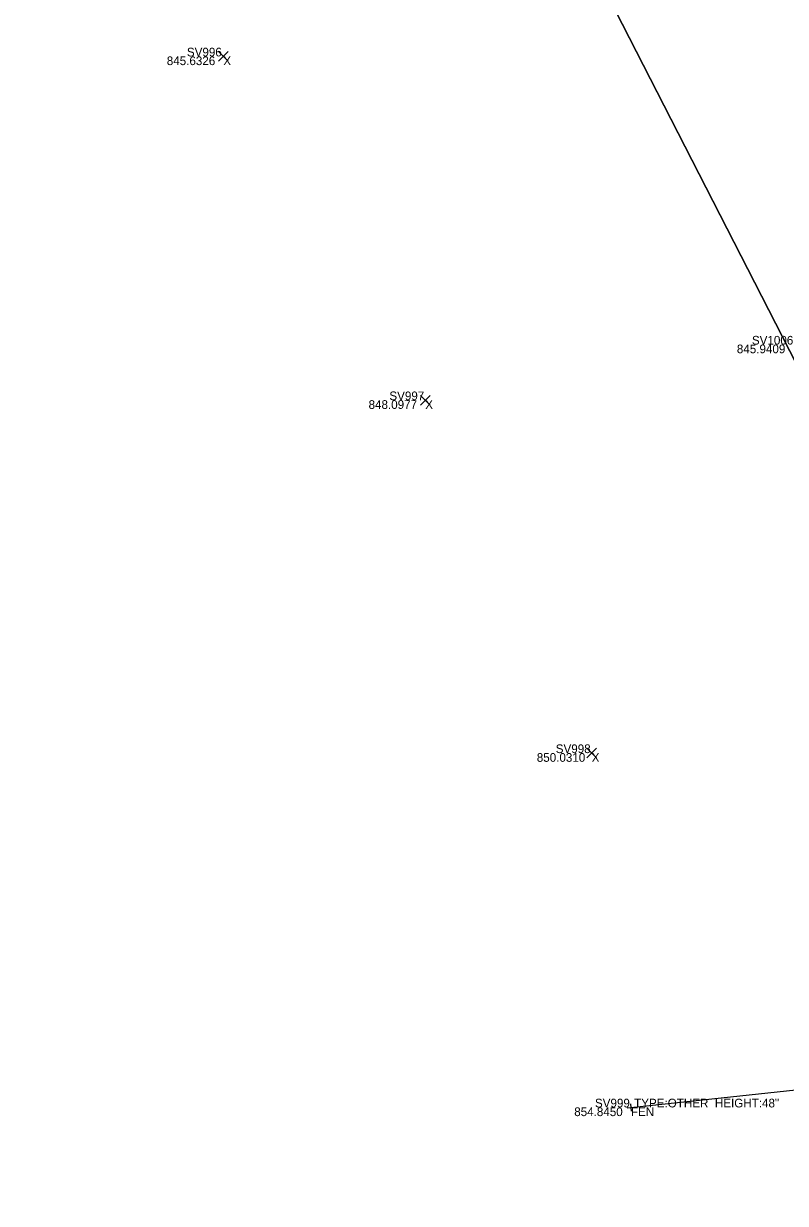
# Model space of a CAD drawing. Extents: x 1715717 to 1717046, y 393954 to 396000.
# Drawn here: x 1716325 to 1716377.5, y 394274.3 to 394355.7 of the extents above; entities that cross this region are included whole.
import ezdxf

# ---------------------------------------------------------------- set-up
doc = ezdxf.new("R2010")
doc.units = 0
for name, color, linetype in [('RD_X_Fence', 7, 'Continuous'), ('SV_X_Random_Point', 7, 'Continuous'), ('SV_X_Shot_Marker', 7, 'Continuous'), ('SV_X_Text_Comment', 7, 'Continuous'), ('SV_X_Text_Description', 7, 'Continuous'), ('SV_X_Text_Elevation', 7, 'Continuous'), ('SV_X_Text_Name', 7, 'Continuous'), ('UT_X_Water', 7, 'Continuous')]:
    doc.layers.add(name, color=color, linetype=linetype)

msp = doc.modelspace()

# ---------------------------------------------------------------- linework, layer by layer
at = {"layer": 'RD_X_Fence'}
msp.add_lwpolyline([(1716366.885, 394280.883), (1716383.222, 394282.627), (1716399.923, 394284.657), (1716412.306, 394286.324)], dxfattribs=at)
at = {"layer": 'SV_X_Random_Point'}
for p, q in [((1716338.419, 394353.094), (1716339.086, 394353.761)), ((1716338.419, 394353.761), (1716339.086, 394353.094)), ((1716352.357, 394329.364), (1716353.023, 394330.032)), ((1716352.357, 394330.032), (1716353.023, 394329.364)), ((1716363.844, 394305.007), (1716364.511, 394305.674)), ((1716363.844, 394305.674), (1716364.511, 394305.007))]:
    msp.add_line(p, q, dxfattribs=at)
at = {"layer": 'SV_X_Shot_Marker'}
for p, q in [((1716366.858, 394281.132), (1716366.911, 394280.635)), ((1716366.636, 394280.857), (1716367.133, 394280.91)), ((1716366.885, 394280.883), (1716366.885, 394280.883))]:
    msp.add_line(p, q, dxfattribs=at)
at = {"layer": 'UT_X_Water'}
for points in [[(1716209.422, 394676.603), (1716226.526, 394640.157), (1716246.856, 394599.269), (1716285.844, 394512.956), (1716341.244, 394404.562), (1716383.609, 394321.849), (1716409.424, 394274.269)], [(1716209.432, 394676.557), (1716226.535, 394640.115), (1716246.863, 394599.23), (1716285.847, 394512.924), (1716341.243, 394404.54), (1716383.604, 394321.833), (1716409.417, 394274.258)]]:
    msp.add_lwpolyline(points, dxfattribs=at)

# ---------------------------------------------------------------- texts
at = {"layer": 'SV_X_Text_Comment'}
for s, p in [('X', (1716338.753, 394352.828)), ('X', (1716352.69, 394329.098)), ('X', (1716364.178, 394304.74)), ('FEN', (1716366.885, 394280.283))]:
    msp.add_text(s, height=0.6, dxfattribs=at).set_placement(p)
at = {"layer": 'SV_X_Text_Description'}
msp.add_text(' TYPE:OTHER  HEIGHT:48" ', height=0.6, dxfattribs=at).set_placement((1716366.885, 394280.883))
at = {"layer": 'SV_X_Text_Elevation'}
for s, p in [('845.6326', (1716334.851, 394352.828)), ('845.9409', (1716374.197, 394332.938)), ('848.0977', (1716348.779, 394329.098)), ('850.0310', (1716360.389, 394304.74)), ('854.8450', (1716362.973, 394280.283))]:
    msp.add_text(s, height=0.6, dxfattribs=at).set_placement(p)
at = {"layer": 'SV_X_Text_Name'}
for s, p in [('SV996', (1716336.24, 394353.428)), ('SV1006', (1716375.237, 394333.537)), ('SV997', (1716350.215, 394329.698)), ('SV998', (1716361.698, 394305.34)), ('SV999', (1716364.404, 394280.883))]:
    msp.add_text(s, height=0.6, dxfattribs=at).set_placement(p)

doc.saveas('drawing.dxf')
